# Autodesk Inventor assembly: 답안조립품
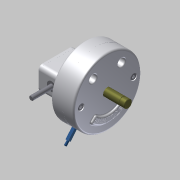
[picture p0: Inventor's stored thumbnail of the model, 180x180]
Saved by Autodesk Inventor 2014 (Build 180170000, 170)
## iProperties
Created: 2015-04
Part Number: 답안조립품
Document SubType Name: Assembly
Designer: Administrator
Mass: 3964.99 g
Surface Area: 3333.71 cm^2
Volume: 1140.85 cm^3
Density: 3.47547 g/cm^3
Author: Administrator
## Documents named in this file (15)
- C:\Documents and Settings\Administrator\바탕 화면\350406V1023\답안조립품.iam
- C:\Documents and Settings\Administrator\바탕 화면\350406V1023\본체.ipt
- C:\Documents and Settings\Administrator\바탕 화면\350406V1023\커버.ipt
- C:\Documents and Settings\Administrator\바탕 화면\350406V1023\M 10 x 35.ipt
- C:\Documents and Settings\Administrator\바탕 화면\350406V1023\커버2.ipt
- C:\Documents and Settings\Administrator\바탕 화면\350406V1023\스프링.ipt
- C:\Documents and Settings\Administrator\바탕 화면\350406V1023\M 5 x 12.ipt
- C:\Documents and Settings\Administrator\바탕 화면\350406V1023\베어링62_22.ipt
- C:\Documents and Settings\Administrator\바탕 화면\350406V1023\축.ipt
- C:\Documents and Settings\Administrator\바탕 화면\350406V1023\멈춤링.ipt
- C:\Documents and Settings\Administrator\바탕 화면\350406V1023\슬라이더2.ipt
- C:\Documents and Settings\Administrator\바탕 화면\350406V1023\슬라이더.ipt
- C:\Documents and Settings\Administrator\바탕 화면\350406V1023\평행핀.ipt
- C:\Documents and Settings\Administrator\바탕 화면\350406V1023\부시.ipt
- C:\Documents and Settings\Administrator\바탕 화면\350406V1023\슬라이더3.ipt
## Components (5 placed, 3 different names)
1. M 10 x 35:1
2. M 10 x 35:2
3. M 5 x 12:1
4. M 5 x 12:2
5. KS B 1320 B B 5 x  20:1
